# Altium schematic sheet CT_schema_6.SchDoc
size 297 x 173 mm
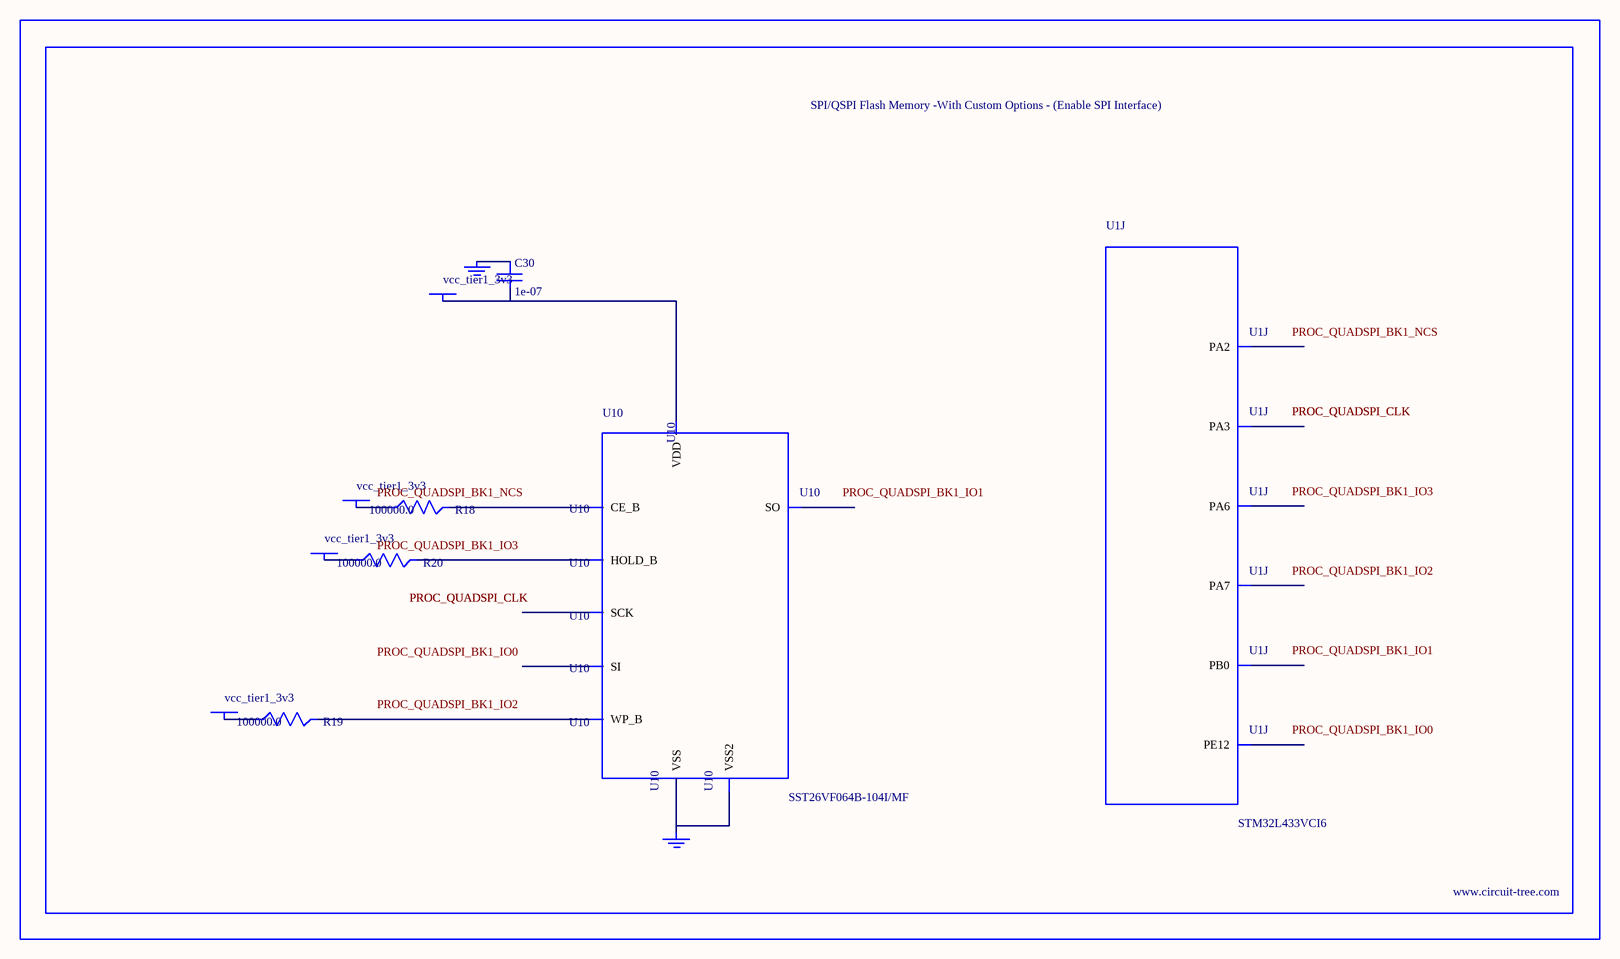
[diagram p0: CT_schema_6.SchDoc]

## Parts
BORDER5  (no value)
C30  1e-07  [C0402]
GND_INSTANCE_5_0  (no value)
GND_INSTANCE_5_1  (no value)
POWER_INSTANCE_5_0  vcc_tier1_3v3
POWER_INSTANCE_5_1  vcc_tier1_3v3
POWER_INSTANCE_5_2  vcc_tier1_3v3
POWER_INSTANCE_5_3  vcc_tier1_3v3
R18  100000.0  [R0603]
R19  100000.0  [R0603]
R20  100000.0  [R0603]
U1  STM32L433VCI6  [UFBGA100]  (part J of 11)
U10  SST26VF064B-104I/MF  [WFDN-8]

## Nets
NetC30_1: C30.1 GND_INSTANCE_5_0.0(GND)
NetC30_2: C30.2 POWER_INSTANCE_5_3.0(PWR) U10.8(VDD)
NetGND_INSTANCE_5_1_0: GND_INSTANCE_5_1.0(GND) U10.4(VSS) U10.9(VSS2)
NetPOWER_INSTANCE_5_0_0: POWER_INSTANCE_5_0.0(PWR) R18.1
NetPOWER_INSTANCE_5_1_0: POWER_INSTANCE_5_1.0(PWR) R19.1
NetPOWER_INSTANCE_5_2_0: POWER_INSTANCE_5_2.0(PWR) R20.1
NetR18_2: R18.2 U10.1(CE_B)
NetR19_2: R19.2 U10.3(WP_B)
NetR20_2: R20.2 U10.7(HOLD_B)

Not connected (* = marked no-connect by the designer): U1 K3(PA2) L3(PA3) L4(PA6) L9(PE12) M4(PA7) M5(PB0); U10 2(SO) 5(SI) 6(SCK)

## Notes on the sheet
- Labels drawn without touching a wire or pin: PROC_QUADSPI_BK1_IO0, PROC_QUADSPI_BK1_IO1, PROC_QUADSPI_BK1_IO2, PROC_QUADSPI_BK1_IO3, PROC_QUADSPI_BK1_NCS

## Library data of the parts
BORDER5 = BORDER_PAGE5
C30 = C0402C104K3RACTU
GND_INSTANCE_5_0 GND_INSTANCE_5_1 = GND
POWER_INSTANCE_5_0-POWER_INSTANCE_5_3 = PWR
R18-R20 = RC0603JR-07100KL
